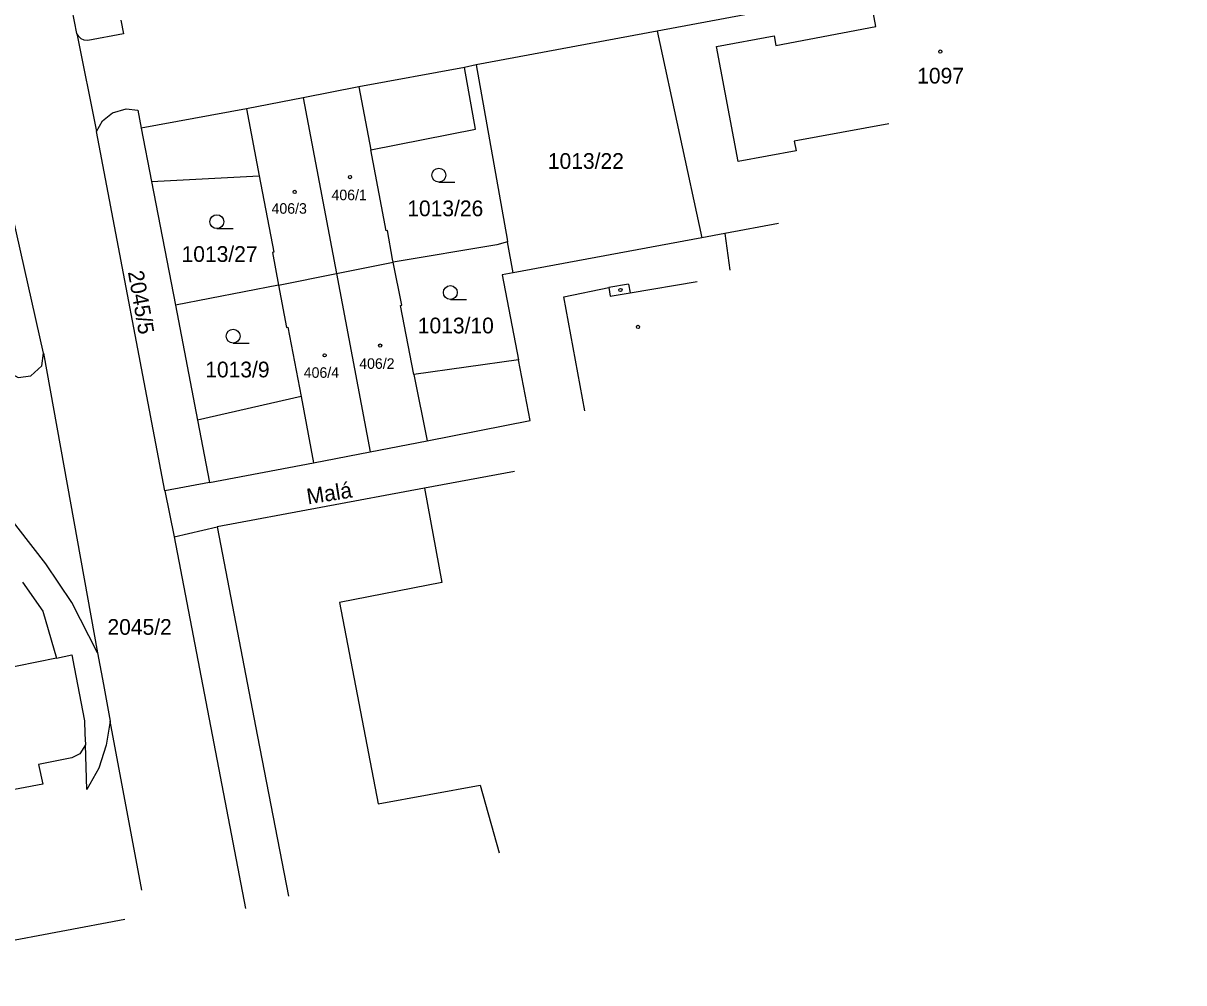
# Model space of a CAD drawing. Extents: x -793666 to -785424, y -1118958 to -1108761.
# Drawn here: x -791983.5 to -791858, y -1109898.9 to -1109795.1 of the extents above; entities that cross this region are included whole.
import ezdxf

# ---------------------------------------------------------------- set-up
doc = ezdxf.new("R2010")
doc.units = 0
for name, color, linetype in [('Hranice parcel', 7, 'Continuous'), ('Parcelní čísla', 7, 'Continuous'), ('Pop  PČ popisy', 7, 'Continuous'), ('Vnitřní kresba', 7, 'Continuous'), ('Značky budov', 7, 'Continuous'), ('Značky kultur', 7, 'Continuous')]:
    doc.layers.add(name, color=color, linetype=linetype)

msp = doc.modelspace()

# ---------------------------------------------------------------- linework, layer by layer
at = {"layer": 'Hranice parcel'}
for p, q in [((-791977.67, -1109796.24), (-791985.8, -1109753.42)), ((-791977.67, -1109796.24), (-791975.55, -1109806.82)), ((-791914.93, -1109795.98), (-791934.5, -1109799.64)), ((-791914.93, -1109795.98), (-791910.09, -1109818.33)), ((-791934.5, -1109799.64), (-791935.77, -1109799.9)), ((-791953.22, -1109803.19), (-791949.61, -1109822.2)), ((-791971.08, -1109804.52), (-791970.71, -1109806.48)), ((-791975.55, -1109806.82), (-791974.89, -1109805.69)), ((-791968.15, -1109845.69), (-791975.55, -1109806.82)), ((-791970.71, -1109806.48), (-791969.59, -1109812.25)), ((-791981.27, -1109830.8), (-791986.38, -1109808.14)), ((-791969.59, -1109812.25), (-791967.02, -1109825.63)), ((-791930.5, -1109822.12), (-791931.1, -1109818.77)), ((-791910.09, -1109818.33), (-791930.5, -1109822.12)), ((-791949.61, -1109822.2), (-791943.49, -1109820.96)), ((-791955.86, -1109823.46), (-791949.61, -1109822.2)), ((-791949.61, -1109822.2), (-791945.95, -1109841.48)), ((-791955.86, -1109823.46), (-791967.02, -1109825.63)), ((-791967.02, -1109825.63), (-791964.63, -1109838.06)), ((-791981.27, -1109830.8), (-791975.42, -1109863.21)), ((-791928.66, -1109838.09), (-791929.92, -1109831.54)), ((-791964.63, -1109838.06), (-791963.33, -1109844.8)), ((-791930.35, -1109843.6), (-791940.07, -1109845.41)), ((-791963.33, -1109844.8), (-791968.15, -1109845.69)), ((-791968.15, -1109845.69), (-791967.14, -1109850.67)), ((-791940.07, -1109845.41), (-791962.5, -1109849.6)), ((-791967.14, -1109850.67), (-791962.5, -1109849.6)), ((-791967.14, -1109850.67), (-791959.45, -1109890.88)), ((-791970.65, -1109888.89), (-791974.06, -1109870.61)), ((-791977.34, -1109874.14), (-791978.21, -1109874.59)), ((-791976.75, -1109873.16), (-791977.34, -1109874.14)), ((-791972.5, -1109892.05), (-792008.86, -1109898.91))]:
    msp.add_line(p, q, dxfattribs=at)
for points in [[(-791975.42, -1109863.21), (-791978.21, -1109857.78), (-791981.04, -1109853.58), (-792018.21, -1109805.69), (-792044.53, -1109772.76), (-792046.81, -1109769.82), (-792049.7, -1109767.06), (-792053.05, -1109764.88), (-792056.76, -1109763.28), (-792060.56, -1109762.21), (-792064.43, -1109761.57), (-792068.68, -1109761.68), (-792072.28, -1109762.62), (-792075.73, -1109764.16)], [(-791858, -1109784.94), (-791892.07, -1109791.53), (-791892.88, -1109791.84), (-791914.93, -1109795.98)], [(-791972.9, -1109794.78), (-791972.62, -1109796.28), (-791976.5, -1109797)], [(-791976.5, -1109797), (-791976.87, -1109796.96), (-791977.2, -1109796.81), (-791977.47, -1109796.58), (-791977.67, -1109796.24)], [(-791935.77, -1109799.9), (-791947.17, -1109802), (-791953.22, -1109803.19)], [(-791943.49, -1109820.96), (-791943.54, -1109820.66), (-791944.07, -1109817.55), (-791944.23, -1109817.58), (-791945.89, -1109808.82), (-791934.56, -1109806.57), (-791935.77, -1109799.9)], [(-791934.5, -1109799.64), (-791931.15, -1109818.48), (-791931.1, -1109818.77)], [(-791953.22, -1109803.19), (-791959.34, -1109804.37), (-791970.71, -1109806.48)], [(-791974.89, -1109805.69), (-791973.81, -1109804.83), (-791972.35, -1109804.39), (-791971.08, -1109804.52)], [(-791969.59, -1109812.25), (-791957.97, -1109811.62), (-791956.39, -1109819.89), (-791956.53, -1109819.92), (-791955.86, -1109823.46)], [(-791901.81, -1109816.79), (-791907.63, -1109817.87), (-791910.09, -1109818.33)], [(-791931.1, -1109818.77), (-791932.26, -1109819.08), (-791943.49, -1109820.96)], [(-791929.92, -1109831.54), (-791941.23, -1109833.12), (-791942.69, -1109825.65), (-791942.54, -1109825.62), (-791943.49, -1109820.96)], [(-791930.5, -1109822.12), (-791931.68, -1109822.34), (-791929.92, -1109831.54)], [(-791955.86, -1109823.46), (-791954.99, -1109828.04), (-791954.85, -1109828.01), (-791953.42, -1109835.49), (-791964.63, -1109838.06)], [(-791985.06, -1109832.85), (-791984.01, -1109833.45), (-791982.65, -1109833.27), (-791981.47, -1109832.2), (-791981.27, -1109830.8)], [(-791945.95, -1109841.48), (-791939.8, -1109840.29), (-791928.66, -1109838.09)], [(-791963.33, -1109844.8), (-791952.1, -1109842.67), (-791945.95, -1109841.48)], [(-791940.07, -1109845.41), (-791938.22, -1109855.62), (-791949.27, -1109857.79), (-791945.08, -1109879.54), (-791934.06, -1109877.53), (-791932.03, -1109884.86)], [(-791962.5, -1109849.6), (-791958.13, -1109872.27), (-791954.79, -1109889.53)], [(-791983.56, -1109855.58), (-791981.36, -1109858.72), (-791979.86, -1109863.81), (-791978.2, -1109863.45), (-791977.95, -1109864.76), (-791976.84, -1109870.56)], [(-791975.42, -1109863.21), (-791974.8, -1109866.66), (-791974.06, -1109870.61)], [(-791976.84, -1109870.56), (-791976.79, -1109872), (-791976.75, -1109873.16)], [(-791974.06, -1109870.61), (-791974.51, -1109873.21), (-791975.29, -1109875.68), (-791976.6, -1109877.99), (-791976.75, -1109873.16)], [(-791978.21, -1109874.59), (-791981.82, -1109875.29), (-791981.33, -1109877.41), (-792009.72, -1109882.75), (-792011.35, -1109883.02), (-792012.97, -1109882.81)]]:
    msp.add_lwpolyline(points, dxfattribs=at)
at = {"layer": 'Vnitřní kresba'}
for p, q in [((-791891.31, -1109795.47), (-791891.67, -1109793.52)), ((-791902.1, -1109797.52), (-791891.31, -1109795.47)), ((-791908.53, -1109797.65), (-791902.29, -1109796.48)), ((-791906.18, -1109810.1), (-791908.53, -1109797.65)), ((-791902.29, -1109796.48), (-791902.1, -1109797.52)), ((-791947.17, -1109802), (-791945.89, -1109808.82)), ((-791959.34, -1109804.37), (-791957.97, -1109811.62)), ((-791889.89, -1109806), (-791900.12, -1109807.89)), ((-791899.92, -1109808.92), (-791906.18, -1109810.1)), ((-791900.12, -1109807.89), (-791899.92, -1109808.92)), ((-791907.63, -1109817.87), (-791907.06, -1109821.82)), ((-791925.03, -1109824.73), (-791920.16, -1109823.7)), ((-791918.02, -1109823.34), (-791920.16, -1109823.7)), ((-791920.16, -1109823.7), (-791920, -1109824.64)), ((-791918.02, -1109823.34), (-791917.86, -1109824.29)), ((-791917.86, -1109824.29), (-791910.62, -1109823.07)), ((-791922.77, -1109837.04), (-791925.03, -1109824.73)), ((-791920, -1109824.64), (-791917.86, -1109824.29)), ((-791941.23, -1109833.12), (-791939.8, -1109840.29)), ((-791953.42, -1109835.49), (-791952.1, -1109842.67)), ((-791979.86, -1109863.81), (-791986.75, -1109865.19))]:
    msp.add_line(p, q, dxfattribs=at)
at = {"layer": 'Značky budov'}
for centre in [(-791884.32, -1109798.19), (-791948.14, -1109811.77), (-791954.12, -1109813.37), (-791918.9, -1109823.98), (-791917, -1109827.97), (-791944.88, -1109829.99), (-791950.88, -1109831.05)]:
    msp.add_circle(centre, 0.175, dxfattribs=at)
at = {"layer": 'Značky kultur'}
for p, q in [((-791938.54, -1109812.31), (-791936.79, -1109812.31)), ((-791962.53, -1109817.34), (-791960.78, -1109817.34)), ((-791937.29, -1109825.01), (-791935.54, -1109825.01)), ((-791960.78, -1109829.72), (-791959.03, -1109829.72))]:
    msp.add_line(p, q, dxfattribs=at)
for centre in [(-791938.54, -1109811.56), (-791962.53, -1109816.59), (-791937.29, -1109824.26), (-791960.78, -1109828.97)]:
    msp.add_circle(centre, 0.75, dxfattribs=at)

# ---------------------------------------------------------------- texts
at = {"layer": 'Parcelní čísla'}
for s, height, p in [('1097', 1.7, (-791886.82, -1109801.65)), ('1013/22', 1.7, (-791926.75, -1109810.88)), ('406/1', 1.14, (-791950.14, -1109814.27)), ('406/3', 1.14, (-791956.62, -1109815.73)), ('1013/26', 1.7, (-791941.95, -1109816)), ('1013/27', 1.7, (-791966.35, -1109820.94)), ('1013/10', 1.7, (-791940.81, -1109828.67)), ('406/2', 1.14, (-791947.14, -1109832.51)), ('1013/9', 1.7, (-791963.79, -1109833.43)), ('406/4', 1.14, (-791953.14, -1109833.48)), ('2045/2', 1.7, (-791974.36, -1109861.27))]:
    msp.add_text(s, height=height, dxfattribs=at).set_placement(p)
msp.add_text('2045/5', height=1.7, rotation=280, dxfattribs=at).set_placement((-791972.16, -1109822.03))
at = {"layer": 'Pop  PČ popisy'}
msp.add_text('Malá', height=1.7, rotation=9, dxfattribs=at).set_placement((-791952.69, -1109847.18))

doc.saveas('drawing.dxf')
